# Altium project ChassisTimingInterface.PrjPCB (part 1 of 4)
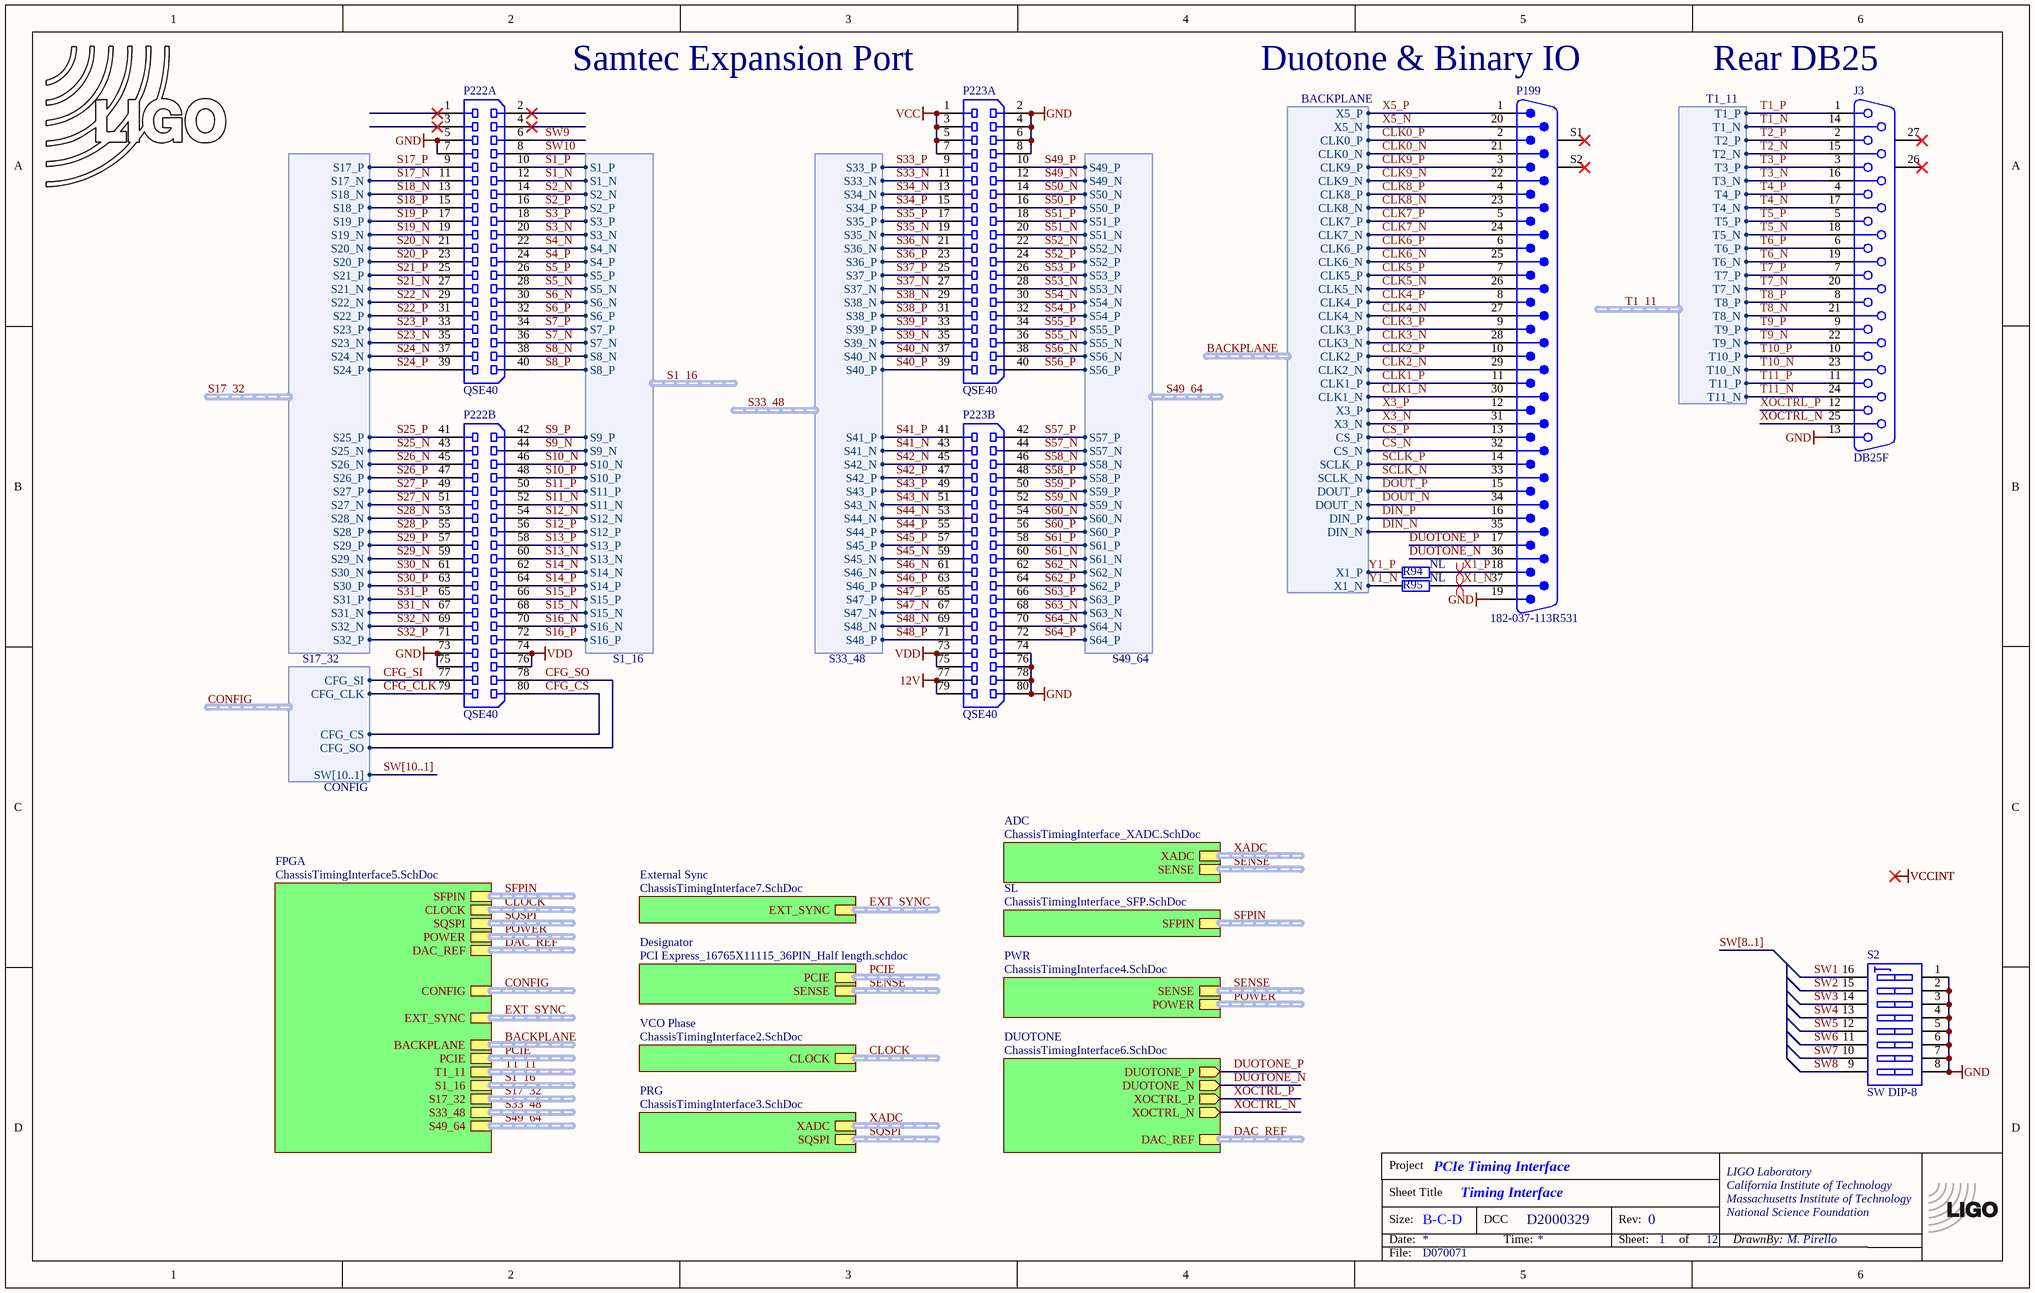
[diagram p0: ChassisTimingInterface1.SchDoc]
SHEETSIZE: B-C-D; REV: 0; PROJECT: PCIe Timing Interface; Eng: M. Pirello; DCC: D2000329
11 sheets, 554 parts. Net scope: hierarchical (ports join the sheet entries above them; power ports are global).
Board file: PCI Express_16765X11115_36PIN_Half length.PCBDOC
Sheets:
  ChassisTimingInterface1.SchDoc
    VCO Phase = ChassisTimingInterface2.SchDoc
    PWR = ChassisTimingInterface4.SchDoc
    PRG = ChassisTimingInterface3.SchDoc
    FPGA = ChassisTimingInterface5.SchDoc
      FPGA = FPGA_ARTIX7.SchDoc
    Designator = PCI Express_16765X11115_36PIN_Half length.schdoc
    DUOTONE = ChassisTimingInterface6.SchDoc
    SL = ChassisTimingInterface_SFP.SchDoc
    External Sync = ChassisTimingInterface7.SchDoc
    ADC = ChassisTimingInterface_XADC.SchDoc

## Sheet ChassisTimingInterface1.SchDoc: Timing Interface
size B; Engineer: Daniel Sigg; DocumentNumber: 1; Revision: C; SheetNumber: 1; SheetTotal: 12; PageSetup: Record=PageOptions¦CenterHorizontal=True¦CenterVertical=True¦PrintScale=0.72¦XCorrection=1.00¦YCorrection=1.00¦PrintKind=0¦BorderSize=5000000¦LeftOffset=0¦BottomOffset=0¦Orientation=2¦PaperLength=1000¦PaperWidth=1000¦Scale=100¦PaperSource=7¦PrintQuality=-4¦MediaType=1¦DitherType=10¦PaperKind=Tabloid¦PrintScaleMode=1

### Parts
(Parts that share a designator on the sheet are numbered #1, #2 ... from top to bottom, then left to right.)
*#1  TitleBlock  (value not drawn)  (graphical)
J3  DB25F  [DB25F-RA]
LOGO1  LIGO logo  [LIGO-LOGO-SM]  (value not drawn)  (no BOM)
P199  182-037-113R531  [NORCO-182-037-113R531_V]
P222  QSE40  [QSE040]  (parts A,B of 2)
P223  QSE40  [QSE040]  (parts A,B of 2)
R94  NL  [CR1005-0402]
R95  NL  [CR1005-0402]
S2  SW DIP-8  [DIP_SW_8WAY_SMD_SIDE]

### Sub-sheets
ADC = ChassisTimingInterface_XADC.SchDoc: XADC (harness XADC), SENSE (harness SENSE)
Designator = PCI Express_16765X11115_36PIN_Half length.schdoc: PCIE (harness PCIE), SENSE (harness SENSE)
DUOTONE = ChassisTimingInterface6.SchDoc: DUOTONE_N (out), DUOTONE_P (out), XOCTRL_P (out), XOCTRL_N (out), DAC_REF (harness DAC_REF)
External Sync = ChassisTimingInterface7.SchDoc: EXT_SYNC (harness EXT_SYNC)
FPGA = ChassisTimingInterface5.SchDoc: S1_16 (harness S1_16), S17_32 (harness S17_32), S33_48 (harness S33_48), S49_64 (harness S49_64), T1_11 (harness T1_11), CLOCK (harness CLOCK), PCIE (harness PCIE), POWER (harness POWER), SQSPI (harness SQSPI), DAC_REF (harness DAC_REF), CONFIG (harness CONFIG), BACKPLANE (harness BACKPLANE), SFPIN (harness SFPIN), EXT_SYNC (harness EXT_SYNC)
PRG = ChassisTimingInterface3.SchDoc: SQSPI (harness SQSPI), XADC (harness XADC)
PWR = ChassisTimingInterface4.SchDoc: POWER (harness POWER), SENSE (harness SENSE)
SL = ChassisTimingInterface_SFP.SchDoc: SFPIN (harness SFPIN)
VCO Phase = ChassisTimingInterface2.SchDoc: CLOCK (harness CLOCK)

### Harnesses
S1_16: S1_N, S1_P, S2_N, S2_P, S3_N, S3_P, S4_N, S4_P, S5_N, S5_P, S6_N, S6_P, S7_N, S7_P, S8_N, S8_P, S9_N, S9_P, S10_N, S10_P, S11_N, S11_P, S12_N, S12_P, S13_N, S13_P, S14_N, S14_P, S15_N, S15_P, S16_N, S16_P
S17_32: S17_N, S17_P, S18_N, S18_P, S19_N, S19_P, S20_N, S20_P, S21_N, S21_P, S22_N, S22_P, S23_N, S23_P, S24_N, S24_P, S25_N, S25_P, S26_N, S26_P, S27_N, S27_P, S28_N, S28_P, S29_N, S29_P, S30_N, S30_P, S31_N, S31_P, S32_N, S32_P
S33_48: S33_P, S33_N, S34_P, S34_N, S35_P, S35_N, S36_N, S36_P, S37_P, S37_N, S38_N, S38_P, S39_P, S39_N, S40_N, S40_P, S41_P, S41_N, S42_N, S42_P, S43_P, S43_N, S44_N, S44_P, S45_P, S45_N, S46_N, S46_P, S47_P, S47_N, S48_N, S48_P
S49_64: S49_P, S49_N, S50_N, S50_P, S51_P, S51_N, S52_N, S52_P, S53_P, S53_N, S54_N, S54_P, S55_P, S55_N, S56_N, S56_P, S57_P, S57_N, S58_N, S58_P, S59_P, S59_N, S60_N, S60_P, S61_P, S61_N, S62_N, S62_P, S63_P, S63_N, S64_N, S64_P
T1_11: T1_P, T1_N, T2_P, T2_N, T3_P, T3_N, T4_P, T4_N, T5_P, T5_N, T6_P, T6_N, T7_P, T7_N, T8_P, T8_N, T9_P, T9_N, T10_P, T10_N, T11_P, T11_N
CONFIG: CFG_CLK, CFG_CS, CFG_SI, CFG_SO, SW[10..1]
BACKPLANE: DIN_N, DIN_P, DOUT_N, DOUT_P, SCLK_N, SCLK_P, CS_N, CS_P, X3_N, X3_P, CLK1_N, CLK1_P, CLK2_N, CLK2_P, CLK3_N, CLK3_P, CLK4_N, CLK4_P, CLK5_N, CLK5_P, CLK6_N, CLK6_P, CLK7_N, CLK7_P, CLK8_N, CLK8_P, CLK9_N, CLK9_P, CLK0_N, CLK0_P, X5_N, X5_P, X1_P, X1_N

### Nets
12V: P223.77 P223.79
GND: J3.13 P199.19 P222.5 P222.7 P222.73 P222.75 P222.81 P222.82 P222.83 P222.84 P222.85 P222.86 P222.87 P222.88 P223.2 P223.4 P223.6 P223.8 P223.74 P223.76 P223.78 P223.80 P223.81 P223.82 P223.83 P223.84 P223.85 P223.86 P223.87 P223.88 S2.1(A1) S2.2(A2) S2.3(A3) S2.4(A4) S2.5(A5) S2.6(A6) S2.7(A7) S2.8(A8)
VCC: P223.1 P223.3 P223.5 P223.7
VDD: P222.74 P222.76 P223.73 P223.75
CFG_CLK: P222.79 ; sheet FPGA/CONFIG.CFG_CLK
CFG_CS: P222.80 ; sheet FPGA/CONFIG.CFG_CS
CFG_SI: P222.77 ; sheet FPGA/CONFIG.CFG_SI
CFG_SO: P222.78 ; sheet FPGA/CONFIG.CFG_SO
CLK0_N: P199.21 ; sheet FPGA/BACKPLANE.CLK0_N  [project net BACKPLANE.CLK0_N]
CLK0_P: P199.2 ; sheet FPGA/BACKPLANE.CLK0_P  [project net BACKPLANE.CLK0_P]
CLK1_N: P199.30 ; sheet FPGA/BACKPLANE.CLK1_N  [project net BACKPLANE.CLK1_N]
CLK1_P: P199.11 ; sheet FPGA/BACKPLANE.CLK1_P  [project net BACKPLANE.CLK1_P]
CLK2_N: P199.29 ; sheet FPGA/BACKPLANE.CLK2_N  [project net BACKPLANE.CLK2_N]
CLK2_P: P199.10 ; sheet FPGA/BACKPLANE.CLK2_P  [project net BACKPLANE.CLK2_P]
CLK3_N: P199.28 ; sheet FPGA/BACKPLANE.CLK3_N  [project net BACKPLANE.CLK3_N]
CLK3_P: P199.9 ; sheet FPGA/BACKPLANE.CLK3_P  [project net BACKPLANE.CLK3_P]
CLK4_N: P199.27 ; sheet FPGA/BACKPLANE.CLK4_N  [project net BACKPLANE.CLK4_N]
CLK4_P: P199.8 ; sheet FPGA/BACKPLANE.CLK4_P  [project net BACKPLANE.CLK4_P]
CLK5_N: P199.26 ; sheet FPGA/BACKPLANE.CLK5_N  [project net BACKPLANE.CLK5_N]
CLK5_P: P199.7 ; sheet FPGA/BACKPLANE.CLK5_P  [project net BACKPLANE.CLK5_P]
CLK6_N: P199.25 ; sheet FPGA/BACKPLANE.CLK6_N  [project net BACKPLANE.CLK6_N]
CLK6_P: P199.6 ; sheet FPGA/BACKPLANE.CLK6_P  [project net BACKPLANE.CLK6_P]
CLK7_N: P199.24 ; sheet FPGA/BACKPLANE.CLK7_N  [project net BACKPLANE.CLK7_N]
CLK7_P: P199.5 ; sheet FPGA/BACKPLANE.CLK7_P  [project net BACKPLANE.CLK7_P]
CLK8_N: P199.23 ; sheet FPGA/BACKPLANE.CLK8_N  [project net BACKPLANE.CLK8_N]
CLK8_P: P199.4 ; sheet FPGA/BACKPLANE.CLK8_P  [project net BACKPLANE.CLK8_P]
CLK9_N: P199.22 ; sheet FPGA/BACKPLANE.CLK9_N  [project net BACKPLANE.CLK9_N]
CLK9_P: P199.3 ; sheet FPGA/BACKPLANE.CLK9_P  [project net BACKPLANE.CLK9_P]
CS_N: P199.32 ; sheet FPGA/BACKPLANE.CS_N  [project net BACKPLANE.CS_N]
CS_P: P199.13 ; sheet FPGA/BACKPLANE.CS_P  [project net BACKPLANE.CS_P]
DIN_N: P199.35 ; sheet FPGA/BACKPLANE.DIN_N  [project net BACKPLANE.DIN_N]
DIN_P: P199.16 ; sheet FPGA/BACKPLANE.DIN_P  [project net BACKPLANE.DIN_P]
DOUT_N: P199.34 ; sheet FPGA/BACKPLANE.DOUT_N  [project net BACKPLANE.DOUT_N]
DOUT_P: P199.15 ; sheet FPGA/BACKPLANE.DOUT_P  [project net BACKPLANE.DOUT_P]
DUOTONE_N: P199.36 ; sheet DUOTONE/DUOTONE_N
DUOTONE_P: P199.17 ; sheet DUOTONE/DUOTONE_P
S1_N: P222.12 ; sheet FPGA/S1_16.S1_N  [project net S1_16.S1_N]
S1_P: P222.10 ; sheet FPGA/S1_16.S1_P  [project net S1_16.S1_P]
S2_N: P222.14 ; sheet FPGA/S1_16.S2_N  [project net S1_16.S2_N]
S2_P: P222.16 ; sheet FPGA/S1_16.S2_P  [project net S1_16.S2_P]
S3_N: P222.20 ; sheet FPGA/S1_16.S3_N  [project net S1_16.S3_N]
S3_P: P222.18 ; sheet FPGA/S1_16.S3_P  [project net S1_16.S3_P]
S4_N: P222.22 ; sheet FPGA/S1_16.S4_N  [project net S1_16.S4_N]
S4_P: P222.24 ; sheet FPGA/S1_16.S4_P  [project net S1_16.S4_P]
S5_N: P222.28 ; sheet FPGA/S1_16.S5_N  [project net S1_16.S5_N]
S5_P: P222.26 ; sheet FPGA/S1_16.S5_P  [project net S1_16.S5_P]
S6_N: P222.30 ; sheet FPGA/S1_16.S6_N  [project net S1_16.S6_N]
S6_P: P222.32 ; sheet FPGA/S1_16.S6_P  [project net S1_16.S6_P]
S7_N: P222.36 ; sheet FPGA/S1_16.S7_N  [project net S1_16.S7_N]
S7_P: P222.34 ; sheet FPGA/S1_16.S7_P  [project net S1_16.S7_P]
S8_N: P222.38 ; sheet FPGA/S1_16.S8_N  [project net S1_16.S8_N]
S8_P: P222.40 ; sheet FPGA/S1_16.S8_P  [project net S1_16.S8_P]
S9_N: P222.44 ; sheet FPGA/S1_16.S9_N  [project net S1_16.S9_N]
S9_P: P222.42 ; sheet FPGA/S1_16.S9_P  [project net S1_16.S9_P]
S10_N: P222.46 ; sheet FPGA/S1_16.S10_N
S10_P: P222.48 ; sheet FPGA/S1_16.S10_P
S11_N: P222.52 ; sheet FPGA/S1_16.S11_N
S11_P: P222.50 ; sheet FPGA/S1_16.S11_P
S12_N: P222.54 ; sheet FPGA/S1_16.S12_N
S12_P: P222.56 ; sheet FPGA/S1_16.S12_P
S13_N: P222.60 ; sheet FPGA/S1_16.S13_N
S13_P: P222.58 ; sheet FPGA/S1_16.S13_P
S14_N: P222.62 ; sheet FPGA/S1_16.S14_N
S14_P: P222.64 ; sheet FPGA/S1_16.S14_P
S15_N: P222.68 ; sheet FPGA/S1_16.S15_N
S15_P: P222.66 ; sheet FPGA/S1_16.S15_P
S16_N: P222.70 ; sheet FPGA/S1_16.S16_N
S16_P: P222.72 ; sheet FPGA/S1_16.S16_P
S17_N: P222.11 ; sheet FPGA/S17_32.S17_N  [project net S17_32.S17_N]
S17_P: P222.9 ; sheet FPGA/S17_32.S17_P  [project net S17_32.S17_P]
S18_N: P222.13 ; sheet FPGA/S17_32.S18_N  [project net S17_32.S18_N]
S18_P: P222.15 ; sheet FPGA/S17_32.S18_P  [project net S17_32.S18_P]
S19_N: P222.19 ; sheet FPGA/S17_32.S19_N  [project net S17_32.S19_N]
S19_P: P222.17 ; sheet FPGA/S17_32.S19_P  [project net S17_32.S19_P]
S20_N: P222.21 ; sheet FPGA/S17_32.S20_N  [project net S17_32.S20_N]
S20_P: P222.23 ; sheet FPGA/S17_32.S20_P  [project net S17_32.S20_P]
S21_N: P222.27 ; sheet FPGA/S17_32.S21_N  [project net S17_32.S21_N]
S21_P: P222.25 ; sheet FPGA/S17_32.S21_P  [project net S17_32.S21_P]
S22_N: P222.29 ; sheet FPGA/S17_32.S22_N  [project net S17_32.S22_N]
S22_P: P222.31 ; sheet FPGA/S17_32.S22_P  [project net S17_32.S22_P]
S23_N: P222.35 ; sheet FPGA/S17_32.S23_N  [project net S17_32.S23_N]
S23_P: P222.33 ; sheet FPGA/S17_32.S23_P  [project net S17_32.S23_P]
S24_N: P222.37 ; sheet FPGA/S17_32.S24_N  [project net S17_32.S24_N]
S24_P: P222.39 ; sheet FPGA/S17_32.S24_P  [project net S17_32.S24_P]
S25_N: P222.43 ; sheet FPGA/S17_32.S25_N  [project net S17_32.S25_N]
S25_P: P222.41 ; sheet FPGA/S17_32.S25_P  [project net S17_32.S25_P]
S26_N: P222.45 ; sheet FPGA/S17_32.S26_N  [project net S17_32.S26_N]
S26_P: P222.47 ; sheet FPGA/S17_32.S26_P  [project net S17_32.S26_P]
S27_N: P222.51 ; sheet FPGA/S17_32.S27_N  [project net S17_32.S27_N]
S27_P: P222.49 ; sheet FPGA/S17_32.S27_P  [project net S17_32.S27_P]
S28_N: P222.53 ; sheet FPGA/S17_32.S28_N  [project net S17_32.S28_N]
S28_P: P222.55 ; sheet FPGA/S17_32.S28_P  [project net S17_32.S28_P]
S29_N: P222.59 ; sheet FPGA/S17_32.S29_N  [project net S17_32.S29_N]
S29_P: P222.57 ; sheet FPGA/S17_32.S29_P  [project net S17_32.S29_P]
S30_N: P222.61 ; sheet FPGA/S17_32.S30_N  [project net S17_32.S30_N]
S30_P: P222.63 ; sheet FPGA/S17_32.S30_P  [project net S17_32.S30_P]
S31_N: P222.67 ; sheet FPGA/S17_32.S31_N  [project net S17_32.S31_N]
S31_P: P222.65 ; sheet FPGA/S17_32.S31_P  [project net S17_32.S31_P]
S32_N: P222.69 ; sheet FPGA/S17_32.S32_N  [project net S17_32.S32_N]
S32_P: P222.71 ; sheet FPGA/S17_32.S32_P  [project net S17_32.S32_P]
S33_N: P223.11 ; sheet FPGA/S33_48.S33_N  [project net S33_48.S33_N]
S33_P: P223.9 ; sheet FPGA/S33_48.S33_P  [project net S33_48.S33_P]
S34_N: P223.13 ; sheet FPGA/S33_48.S34_N  [project net S33_48.S34_N]
S34_P: P223.15 ; sheet FPGA/S33_48.S34_P  [project net S33_48.S34_P]
S35_N: P223.19 ; sheet FPGA/S33_48.S35_N  [project net S33_48.S35_N]
S35_P: P223.17 ; sheet FPGA/S33_48.S35_P  [project net S33_48.S35_P]
S36_N: P223.21 ; sheet FPGA/S33_48.S36_N  [project net S33_48.S36_N]
S36_P: P223.23 ; sheet FPGA/S33_48.S36_P  [project net S33_48.S36_P]
S37_N: P223.27 ; sheet FPGA/S33_48.S37_N  [project net S33_48.S37_N]
S37_P: P223.25 ; sheet FPGA/S33_48.S37_P  [project net S33_48.S37_P]
S38_N: P223.29 ; sheet FPGA/S33_48.S38_N  [project net S33_48.S38_N]
S38_P: P223.31 ; sheet FPGA/S33_48.S38_P  [project net S33_48.S38_P]
S39_N: P223.35 ; sheet FPGA/S33_48.S39_N  [project net S33_48.S39_N]
S39_P: P223.33 ; sheet FPGA/S33_48.S39_P  [project net S33_48.S39_P]
S40_N: P223.37 ; sheet FPGA/S33_48.S40_N  [project net S33_48.S40_N]
S40_P: P223.39 ; sheet FPGA/S33_48.S40_P  [project net S33_48.S40_P]
S41_N: P223.43 ; sheet FPGA/S33_48.S41_N  [project net S33_48.S41_N]
S41_P: P223.41 ; sheet FPGA/S33_48.S41_P  [project net S33_48.S41_P]
S42_N: P223.45 ; sheet FPGA/S33_48.S42_N  [project net S33_48.S42_N]
S42_P: P223.47 ; sheet FPGA/S33_48.S42_P  [project net S33_48.S42_P]
S43_N: P223.51 ; sheet FPGA/S33_48.S43_N  [project net S33_48.S43_N]
S43_P: P223.49 ; sheet FPGA/S33_48.S43_P  [project net S33_48.S43_P]
S44_N: P223.53 ; sheet FPGA/S33_48.S44_N  [project net S33_48.S44_N]
S44_P: P223.55 ; sheet FPGA/S33_48.S44_P  [project net S33_48.S44_P]
S45_N: P223.59 ; sheet FPGA/S33_48.S45_N  [project net S33_48.S45_N]
S45_P: P223.57 ; sheet FPGA/S33_48.S45_P  [project net S33_48.S45_P]
S46_N: P223.61 ; sheet FPGA/S33_48.S46_N  [project net S33_48.S46_N]
S46_P: P223.63 ; sheet FPGA/S33_48.S46_P  [project net S33_48.S46_P]
S47_N: P223.67 ; sheet FPGA/S33_48.S47_N  [project net S33_48.S47_N]
S47_P: P223.65 ; sheet FPGA/S33_48.S47_P  [project net S33_48.S47_P]
S48_N: P223.69 ; sheet FPGA/S33_48.S48_N  [project net S33_48.S48_N]
S48_P: P223.71 ; sheet FPGA/S33_48.S48_P  [project net S33_48.S48_P]
S49_N: P223.12 ; sheet FPGA/S49_64.S49_N  [project net S49_64.S49_N]
S49_P: P223.10 ; sheet FPGA/S49_64.S49_P  [project net S49_64.S49_P]
S50_N: P223.14 ; sheet FPGA/S49_64.S50_N  [project net S49_64.S50_N]
S50_P: P223.16 ; sheet FPGA/S49_64.S50_P  [project net S49_64.S50_P]
S51_N: P223.20 ; sheet FPGA/S49_64.S51_N  [project net S49_64.S51_N]
S51_P: P223.18 ; sheet FPGA/S49_64.S51_P  [project net S49_64.S51_P]
S52_N: P223.22 ; sheet FPGA/S49_64.S52_N  [project net S49_64.S52_N]
S52_P: P223.24 ; sheet FPGA/S49_64.S52_P  [project net S49_64.S52_P]
S53_N: P223.28 ; sheet FPGA/S49_64.S53_N  [project net S49_64.S53_N]
S53_P: P223.26 ; sheet FPGA/S49_64.S53_P  [project net S49_64.S53_P]
S54_N: P223.30 ; sheet FPGA/S49_64.S54_N  [project net S49_64.S54_N]
S54_P: P223.32 ; sheet FPGA/S49_64.S54_P  [project net S49_64.S54_P]
S55_N: P223.36 ; sheet FPGA/S49_64.S55_N  [project net S49_64.S55_N]
S55_P: P223.34 ; sheet FPGA/S49_64.S55_P  [project net S49_64.S55_P]
S56_N: P223.38 ; sheet FPGA/S49_64.S56_N  [project net S49_64.S56_N]
S56_P: P223.40 ; sheet FPGA/S49_64.S56_P  [project net S49_64.S56_P]
S57_N: P223.44 ; sheet FPGA/S49_64.S57_N  [project net S49_64.S57_N]
S57_P: P223.42 ; sheet FPGA/S49_64.S57_P  [project net S49_64.S57_P]
S58_N: P223.46 ; sheet FPGA/S49_64.S58_N  [project net S49_64.S58_N]
S58_P: P223.48 ; sheet FPGA/S49_64.S58_P  [project net S49_64.S58_P]
S59_N: P223.52 ; sheet FPGA/S49_64.S59_N  [project net S49_64.S59_N]
S59_P: P223.50 ; sheet FPGA/S49_64.S59_P  [project net S49_64.S59_P]
S60_N: P223.54 ; sheet FPGA/S49_64.S60_N  [project net S49_64.S60_N]
S60_P: P223.56 ; sheet FPGA/S49_64.S60_P  [project net S49_64.S60_P]
S61_N: P223.60 ; sheet FPGA/S49_64.S61_N  [project net S49_64.S61_N]
S61_P: P223.58 ; sheet FPGA/S49_64.S61_P  [project net S49_64.S61_P]
S62_N: P223.62 ; sheet FPGA/S49_64.S62_N  [project net S49_64.S62_N]
S62_P: P223.64 ; sheet FPGA/S49_64.S62_P  [project net S49_64.S62_P]
S63_N: P223.68 ; sheet FPGA/S49_64.S63_N  [project net S49_64.S63_N]
S63_P: P223.66 ; sheet FPGA/S49_64.S63_P  [project net S49_64.S63_P]
S64_N: P223.70 ; sheet FPGA/S49_64.S64_N  [project net S49_64.S64_N]
S64_P: P223.72 ; sheet FPGA/S49_64.S64_P  [project net S49_64.S64_P]
SCLK_N: P199.33 ; sheet FPGA/BACKPLANE.SCLK_N  [project net BACKPLANE.SCLK_N]
SCLK_P: P199.14 ; sheet FPGA/BACKPLANE.SCLK_P  [project net BACKPLANE.SCLK_P]
SW1: S2.16(B1)
SW2: S2.15(B2)
SW3: S2.14(B3)
SW4: S2.13(B4)
SW5: S2.12(B5)
SW6: S2.11(B6)
SW7: S2.10(B7)
SW8: S2.9(B8)
SW9: P222.6
SW10: P222.8
T1_N: J3.14 ; sheet FPGA/T1_11.T1_N  [project net T1_11.T1_N]
T1_P: J3.1 ; sheet FPGA/T1_11.T1_P  [project net T1_11.T1_P]
T2_N: J3.15 ; sheet FPGA/T1_11.T2_N  [project net T1_11.T2_N]
T2_P: J3.2 ; sheet FPGA/T1_11.T2_P  [project net T1_11.T2_P]
T3_N: J3.16 ; sheet FPGA/T1_11.T3_N  [project net T1_11.T3_N]
T3_P: J3.3 ; sheet FPGA/T1_11.T3_P  [project net T1_11.T3_P]
T4_N: J3.17 ; sheet FPGA/T1_11.T4_N  [project net T1_11.T4_N]
T4_P: J3.4 ; sheet FPGA/T1_11.T4_P  [project net T1_11.T4_P]
T5_N: J3.18 ; sheet FPGA/T1_11.T5_N  [project net T1_11.T5_N]
T5_P: J3.5 ; sheet FPGA/T1_11.T5_P  [project net T1_11.T5_P]
T6_N: J3.19 ; sheet FPGA/T1_11.T6_N  [project net T1_11.T6_N]
T6_P: J3.6 ; sheet FPGA/T1_11.T6_P  [project net T1_11.T6_P]
T7_N: J3.20 ; sheet FPGA/T1_11.T7_N  [project net T1_11.T7_N]
T7_P: J3.7 ; sheet FPGA/T1_11.T7_P  [project net T1_11.T7_P]
T8_N: J3.21 ; sheet FPGA/T1_11.T8_N  [project net T1_11.T8_N]
T8_P: J3.8 ; sheet FPGA/T1_11.T8_P  [project net T1_11.T8_P]
T9_N: J3.22 ; sheet FPGA/T1_11.T9_N  [project net T1_11.T9_N]
T9_P: J3.9 ; sheet FPGA/T1_11.T9_P  [project net T1_11.T9_P]
T10_N: J3.23 ; sheet FPGA/T1_11.T10_N
T10_P: J3.10 ; sheet FPGA/T1_11.T10_P
T11_N: J3.24 ; sheet FPGA/T1_11.T11_N
T11_P: J3.11 ; sheet FPGA/T1_11.T11_P
X1_N: P199.37 R95.2
X1_P: P199.18 R94.2
X3_N: P199.31 ; sheet FPGA/BACKPLANE.X3_N  [project net BACKPLANE.X3_N]
X3_P: P199.12 ; sheet FPGA/BACKPLANE.X3_P  [project net BACKPLANE.X3_P]
X5_N: P199.20 ; sheet FPGA/BACKPLANE.X5_N  [project net BACKPLANE.X5_N]
X5_P: P199.1 ; sheet FPGA/BACKPLANE.X5_P  [project net BACKPLANE.X5_P]
XOCTRL_N: J3.25 ; sheet DUOTONE/XOCTRL_N
XOCTRL_P: J3.12 ; sheet DUOTONE/XOCTRL_P
Y1_N: R95.1 ; sheet FPGA/BACKPLANE.X1_N  [project net BACKPLANE.X1_N]
Y1_P: R94.1 ; sheet FPGA/BACKPLANE.X1_P  [project net BACKPLANE.X1_P]

Not connected (* = marked no-connect by the designer): J3 26(MH1)* 27(MH2)*; P199 S1* S2*; P222 1* 2* 3* 4*

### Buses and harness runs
bus SW[8..1]
bus SW[10..1]
harness BACKPLANE = sheet FPGA/BACKPLANE
harness CLOCK = sheet FPGA/CLOCK
harness CLOCK = sheet VCO Phase/CLOCK
harness CONFIG = sheet FPGA/CONFIG
harness DAC_REF = sheet DUOTONE/DAC_REF
harness DAC_REF = sheet FPGA/DAC_REF
harness EXT_SYNC = sheet External Sync/EXT_SYNC
harness EXT_SYNC = sheet FPGA/EXT_SYNC
harness PCIE = sheet Designator/PCIE
harness PCIE = sheet FPGA/PCIE
harness POWER = sheet FPGA/POWER
harness POWER = sheet PWR/POWER
harness S1_16 = sheet FPGA/S1_16
harness S17_32 = sheet FPGA/S17_32
harness S33_48 = sheet FPGA/S33_48
harness S49_64 = sheet FPGA/S49_64
harness SENSE = sheet ADC/SENSE
harness SENSE = sheet Designator/SENSE
harness SENSE = sheet PWR/SENSE
harness SFPIN = sheet FPGA/SFPIN
harness SFPIN = sheet SL/SFPIN
harness SQSPI = sheet FPGA/SQSPI
harness SQSPI = sheet PRG/SQSPI
harness T1_11 = sheet FPGA/T1_11
harness XADC = sheet ADC/XADC
harness XADC = sheet PRG/XADC

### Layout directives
differential pair: X1_N, X1_P

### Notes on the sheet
- (near P223) Samtec Expansion Port
- (near P199) Duotone & Binary IO
- (near J3) Rear DB25

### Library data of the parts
J3 = DB25F: Receptacle Assembly, 25 Position, Right Angle, .318 Series; Part Number: A32128-ND
LOGO1 = LIGO_logo
P199 = CMP-2000-05512-1: Economy Version Right Angle D-Sub Connector, 5 A, -55 to 105 degC, 37-Pin THD, RoHS, Tray; Manufacturer: Norcomp; Other Related Documents: 182-037-113R531MaterialDeclaration; Gender: Male; Product Training Modules: D-SubConnectors; Package Version: 03/2005, Rev. 9; Flange Feature: Housing/Shell(4-40); Catalog Drawings: 182SeriesFront182SeriesSide; Associated Product: 160-37MA-ND-DUSTCOVERFORD-SUB37MALE; Mating Products: 3237FE-ND-CONNDSUBRCPT37POSSTRSLDCUP3237FER-ND-CONNDSUBRCPT37POSSTRSLDCUP237FE-ND-CONNDSUBRCPT37POSSTRSLDCUP237FER-ND-CONNDSUBRCPT37POSSTRSLDCUP1237FE-ND-CONNDSUBRCPT37POSSTRSLDCUP2237FER-ND-CONNDSUBRCPT37POSSTRSLDCUP2237FE-ND-CONNDSUBRCPT37POSSTRSLDCUP1237FER-ND-CONNDSUBRCPT37POSSTRSLDCUP186-037-292L001-ND-CONNDSUBRCPT37POSSTRIDC186-037-292L551-ND-CONNDSUBRCPT37POSSTRIDC; Online Catalog: 182Series; 3D Model: 182-037-113.pdf182-037-113Ryy1.stp182-037-113Ryy1.igs; Current Rating: 5A; Number of Positions: 37; Connector Type: Plug,MalePins; Other Names: 182-37ME182037113R531
P222 P223 = SAMTEC_QSE40: Samtec hi-speed socket, 0.8mm, 80 pins; Part Number: SAM8124-ND
R94 R95 = ChipRes1: Resistor, surface mount; Tolerance: 1%
S2 = SW DIP-8: DIP Switch, 8 Position, SPST; Part Number: CKN6128CT-ND; Side Part: CKN6147-ND

## Sheet ChassisTimingInterface2.SchDoc: VCO & Phase Detector
size B; DocumentNumber: 2; Revision: C; SheetNumber: 2; SheetTotal: 12
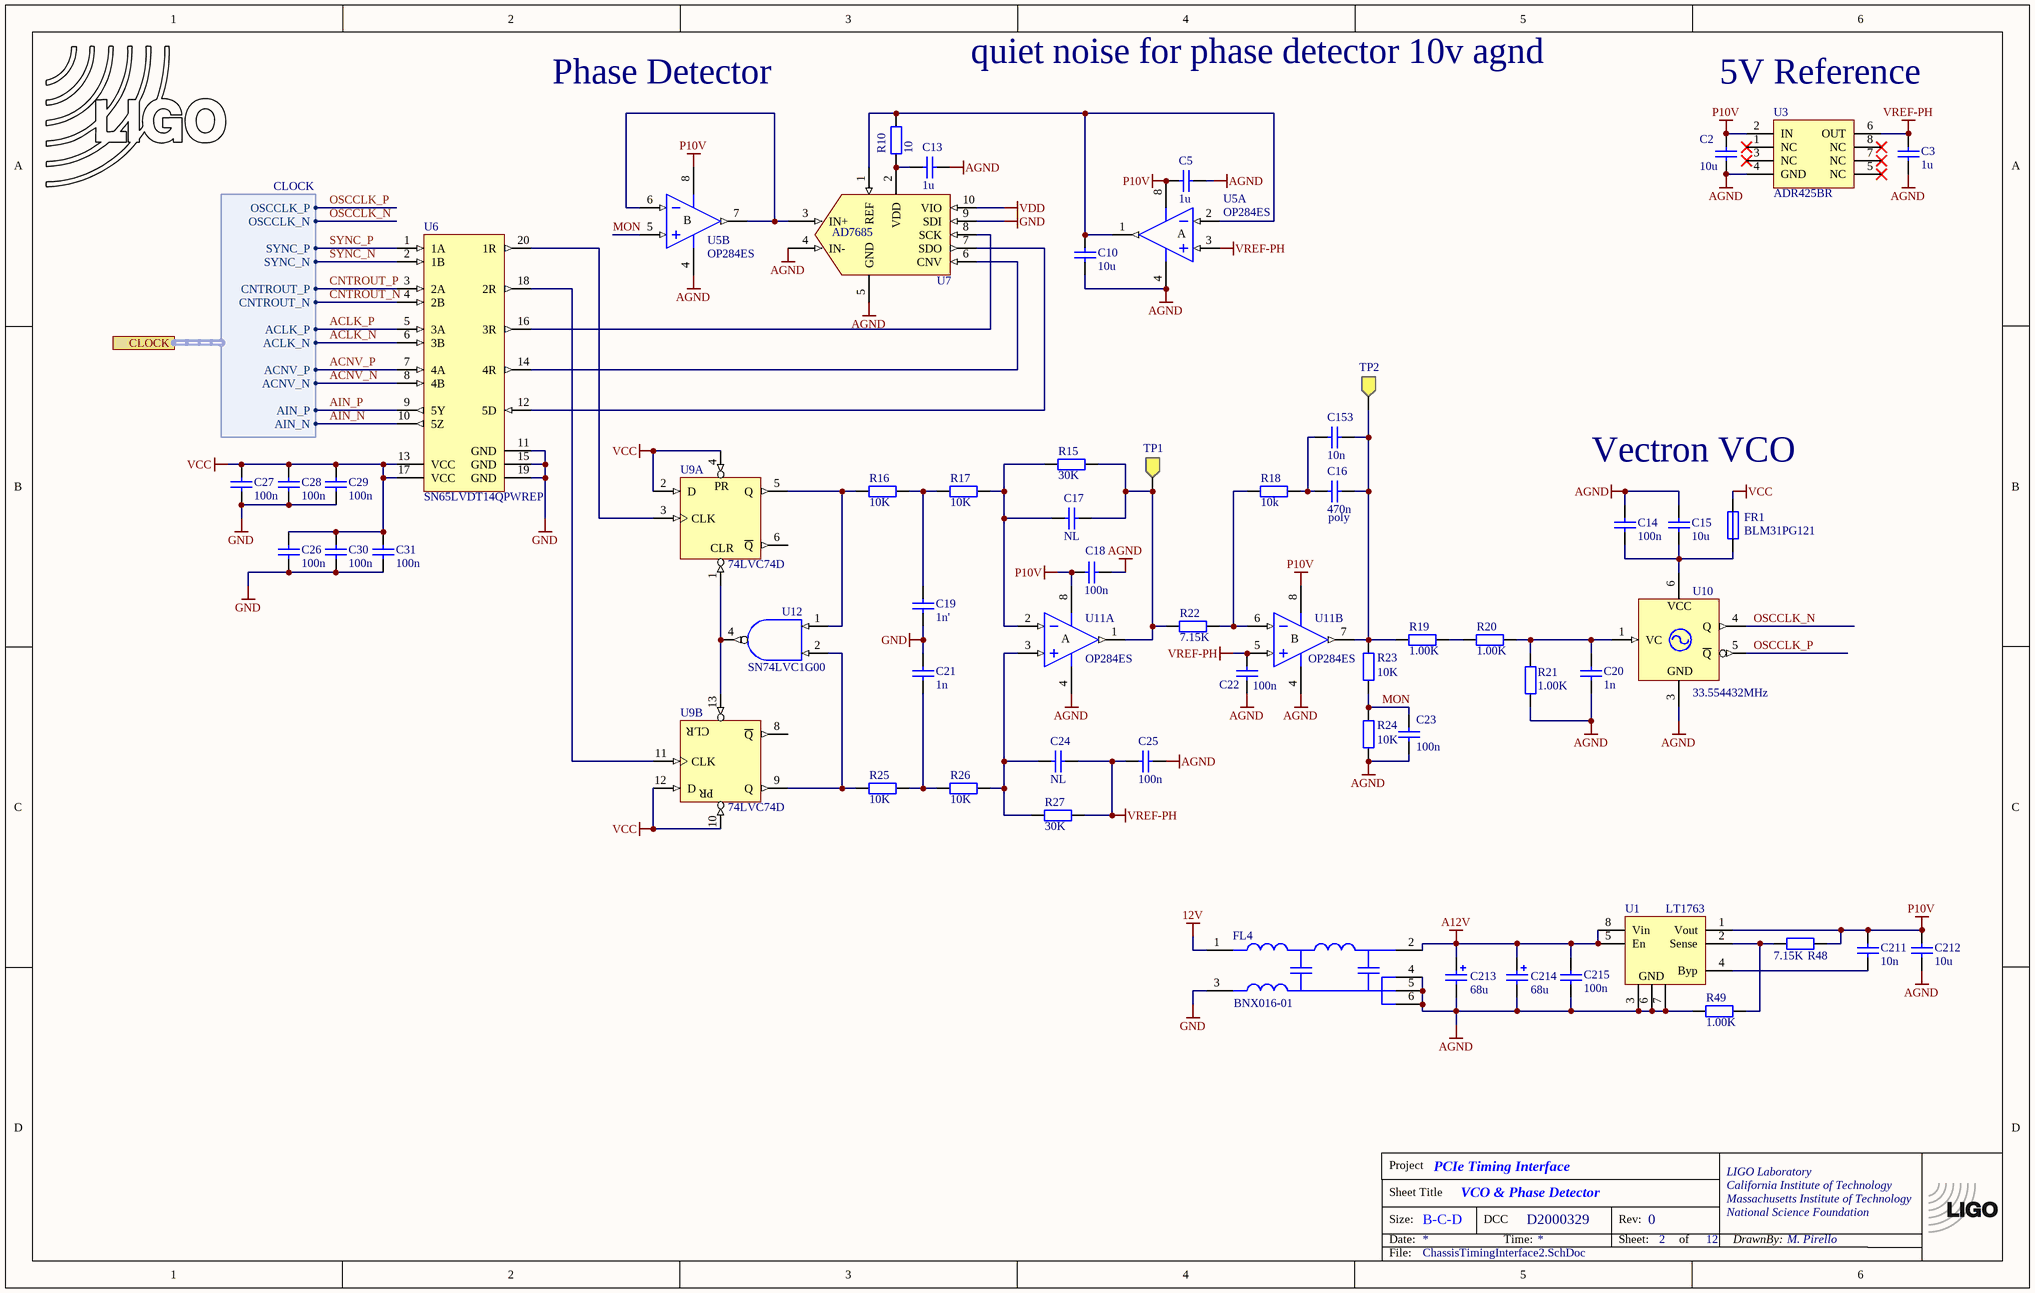
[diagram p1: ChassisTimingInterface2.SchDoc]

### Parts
(Parts that share a designator on the sheet are numbered #1, #2 ... from top to bottom, then left to right.)
*?#1  TitleBlock  (value not drawn)  (graphical)
C2  10u  [CC3216-1206]
C3  1u  [CC2013-0805]
C5  1u  [CC2013-0805]
C10  10u  [CC3216-1206]
C13  1u  [CC2013-0805]
C14  100n  [CC2013-0805]
C15  10u  [CC2013-0805]
C16  470n  [CA053035]
C17  NL  [CC2013-0805]
C18  100n  [CC2013-0805]
C19  1n'  [CC2013-0805]
C20  1n  [CC2013-0805]
C21  1n  [CC2013-0805]
C22  100n  [CC2013-0805]
C23  100n  [CC2013-0805]
C24  NL  [CC2013-0805]
C25  100n  [CC2013-0805]
C26  100n  [CC2013-0805]
C27  100n  [CC2013-0805]
C28  100n  [CC2013-0805]
C29  100n  [CC2013-0805]
C30  100n  [CC2013-0805]
C31  100n  [CC2013-0805]
C153  10n  [CC2013-0805]
C211  10n  [CC2013-0805]
C212  10u  [CC3216-1206]
C213  68u  [TC7343-2917]
C214  68u  [TC7343-2917]
C215  100n  [CC2013-0805]
FL4  BNX016-01  [MURA-BNX016-01_V]
FR1  BLM31PG121  [CC3216-1206]
LOGO2  LIGO logo  [LIGO_LOGO]  (value not drawn)  (graphical)
R10  10  [CR2012-0805]
R15  30K  [CR2012-0805]
R16  10K  [CR2012-0805]
R17  10K  [CR2012-0805]
R18  10k  [CR2012-0805]
R19  1.00K  [CR2012-0805]
R20  1.00K  [CR2012-0805]
R21  1.00K  [CR2012-0805]
R22  7.15K  [CR2012-0805]
R23  10K  [CR2012-0805]
R24  10K  [CR2012-0805]
R25  10K  [CR2012-0805]
R26  10K  [CR2012-0805]
R27  30K  [CR2012-0805]
R48  7.15K  [CR2012-0805]
R49  1.00K  [CR2012-0805]
TP1  Testpoint  [TP1-YLW]  (value not drawn)
TP2  Testpoint  [TP1-YLW]  (value not drawn)
U1  LT1763  [SO-G8]
U3  ADR425BR  [SO-G8]
U5  OP284ES  [SO-8_N]  (parts A,B of 2)
U6  SN65LVDT14QPWREP  [PW0020A_N]
U7  AD7685  [TSSO3x5-G10]
U9  74LVC74D  [TSSOP14]  (parts A,B of 2)
U10  33.554432MHz  [VECTRON_C5310]
U11  OP284ES  [SO-8_N]  (parts A,B of 2)
U12  SN74LVC1G00  [SO-G5/E2.4]

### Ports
CLOCK (harness CLOCK)

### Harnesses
CLOCK: OSCCLK_N, OSCCLK_P, CNTROUT_N, CNTROUT_P, SYNC_N, SYNC_P, ACLK_P, ACLK_N, ACNV_P, ACNV_N, AIN_P, AIN_N

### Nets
12V: FL4.1(B)
A12V: C213.1 C214.1 C215.2 FL4.2(CB) U1.5(En) U1.8(Vin)
AGND: C2.2 C3.1 C5.1 C10.2 C13.1 C14.1 C15.1 C18.1 C20.2 C22.1 C23.1 C25.1 C212.2 C213.2 C214.2 C215.1 FL4.4(CG) FL4.5(CG) FL4.6(CG) R21.2 R24.2 R49.2 U1.3(GND) U1.6(GND) U1.7(GND) U3.4(GND) U5.4(V-) U7.4(IN-) U7.5(GND) U10.3(GND) U11.4(V-)
GND: C19.2 C21.1 C26.1 C27.1 C28.1 C29.1 C30.1 C31.1 FL4.3(PSG) U6.11(GND) U6.15(GND) U6.19(GND) U7.9(SDI) U9.7(GND) U12.3(GND)
P10V: C2.1 C5.2 C18.2 C211.1 C212.1 R48.2 U1.1(Vout) U3.2(IN) U5.8(V+) U11.8(V+)
VCC: C26.2 C27.2 C28.2 C29.2 C30.2 C31.2 FR1.2 U6.13(VCC) U6.17(VCC) U9.2(D) U9.4(PR) U9.10(PR) U9.12(D) U9.14(VCC) U12.5(VCC)
VDD: U7.10(VIO)
VREF-PH: C3.2 C22.2 C24.1 C25.2 R27.2 U3.6(OUT) U5.3(IN+) U11.5(IN+)
ACLK_N: U6.6(3B) ; port CLOCK.ACLK_N  [project net CLOCK.ACLK_N]
ACLK_P: U6.5(3A) ; port CLOCK.ACLK_P  [project net CLOCK.ACLK_P]
ACNV_N: U6.8(4B) ; port CLOCK.ACNV_N  [project net CLOCK.ACNV_N]
ACNV_P: U6.7(4A) ; port CLOCK.ACNV_P  [project net CLOCK.ACNV_P]
AIN_N: U6.10(5Z) ; port CLOCK.AIN_N  [project net CLOCK.AIN_N]
AIN_P: U6.9(5Y) ; port CLOCK.AIN_P  [project net CLOCK.AIN_P]
CNTROUT_N: U6.4(2B) ; port CLOCK.CNTROUT_N  [project net CLOCK.CNTROUT_N]
CNTROUT_P: U6.3(2A) ; port CLOCK.CNTROUT_P  [project net CLOCK.CNTROUT_P]
MON: C23.2 R23.2 R24.1 U5.5(IN+)
OSCCLK_N: U10.4(Q) ; port CLOCK.OSCCLK_N  [project net CLOCK.OSCCLK_N]
OSCCLK_P: U10.5(~{Q}) ; port CLOCK.OSCCLK_P  [project net CLOCK.OSCCLK_P]
SYNC_N: U6.2(1B) ; port CLOCK.SYNC_N  [project net CLOCK.SYNC_N]
SYNC_P: U6.1(1A) ; port CLOCK.SYNC_P  [project net CLOCK.SYNC_P]
NetC10_1: C10.1 R10.2 U5.1(OUT) U5.2(IN-) U7.1(REF)
NetC13_2: C13.2 R10.1 U7.2(VDD)
NetC14_2: C14.2 C15.2 FR1.1 U10.6(VDD)
NetC16_1: C16.1 C153.2 R18.2
NetC16_2: C16.2 C153.1 R19.2 R23.1 TP2.1 U11.7(OUT)
NetC17_1: C17.1 R15.2 R22.1 TP1.1 U11.1(OUT)
NetC17_2: C17.2 R15.1 R17.2 U11.2(IN-)
NetC19_1: C19.1 R16.2 R17.1
NetC20_1: C20.1 R20.1 R21.1 U10.1(VC)
NetC21_2: C21.2 R25.2 R26.1
NetC24_2: C24.2 R26.2 R27.1 U11.3(IN+)
NetC211_2: C211.2 U1.4(Byp)
NetR16_1: R16.1 U9.5(Q) U12.1
NetR18_1: R18.1 R22.2 U11.6(IN-)
NetR19_1: R19.1 R20.2
NetR25_1: R25.1 U9.9(Q) U12.2
NetR48_1: R48.1 R49.1 U1.2(Sense)
NetU5_6: U5.6(IN-) U5.7(OUT) U7.3(IN+)
NetU6_12: U6.12(5D) U7.7(SDO)
NetU6_14: U6.14(4R) U7.6(CNV)
NetU6_16: U6.16(3R) U7.8(SCK)
NetU6_18: U6.18(2R) U9.11(CLK)
NetU6_20: U6.20(1R) U9.3(CLK)
NetU9_1: U9.1(CLR) U9.13(CLR) U12.4

Not connected (* = marked no-connect by the designer): U3 1(NC)* 3(NC)* 5(NC)* 7(NC)* 8(NC)*; U9 6(~{Q}) 8(~{Q}); U10 2(NC)

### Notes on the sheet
- Phase Detector
- quiet noise for phase detector 10v agnd
- 5V Reference
- Vectron VCO
- (near C16) poly

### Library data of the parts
C2 C3 C5 C10 C13-C15 C17-C31 C153 = ChipCap: Capacitor, surface mount; Tolerance: 10%
C16 = CapFilmAxial: Film Capacitor, axial lead; Tolerance: 1%; Voltage Rating: 50V
C211 = ChipCap: Capacitor, surface mount; Part Number: 490-1642-1-ND; Tolerance: 10%
C212 = ChipCap: Capacitor, surface mount; Part Number: PCC2414CT-ND; Tolerance: 10%; Voltage Rating: 25V
C213 C214 = ChipTantalum: Tantalum capacitor, surface mount; Part Number: 399-3908-1-ND; Tolerance: 20%; Voltage Rating: 25V
C215 = ChipCap: Capacitor, surface mount; Part Number: 478-1395-1-ND; Tolerance: 10%
FL4 = CMP-2000-05960-1: Block Type EMIFIL(R) Reference Specification, 15 A, 25 V, -40 to 125 degC, 6-Pin THD, RoHS, Bulk; Manufacturer: Murata; Maximum Current Rating: 15A; Operating Frequency: 100kHz→1GHz; Maximum Voltage Rating: 25Vdc
FR1 = BLM31PG121SN1: ferrite bead, 120Ohm at 100MHz, 1206
LOGO2 = LIGO_logo
R10 R15-R27 = ChipRes1: Resistor, surface mount; Tolerance: 1%
R48 = ChipRes1: Resistor, surface mount; Part Number: RG20P7.15KBCT-ND; Tolerance: 0.1%
R49 = ChipRes1: Resistor, surface mount; Part Number: RG20P1.0KBCT-ND; Tolerance: 0.1%
TP1 TP2 = TP_SIGNAL: Testpoint, yellow; Part Number: 5009K-ND
U1 = LT1763: Positive voltage regulator; Part Number: LT1763CS8#PBF-ND
U3 = ADR292ER: Low-Noise Micropower Precision Voltage Reference; Part Number: ADR425BRZ-ND
U5 U11 = OP284ES: Precision Rail-to-Rail Input and Output Operational Amplifier
U6 = CMP-0327-00205-3: 125 Mbps Enhanced Product Memorystick? Interconnect Extender Chipset with LVDS and LVTTL, 1 Tx and 4 Rx, -55 to +125 degC, 20-pin TSSOP (PW), Green (RoHS & no Sb/Br); Part-to-Part Skew(Max)(ps): 1000; Manufacturer: Texas Instruments; No. of Tx: 1; ESD HBM(kV): 12; ICC(Max)(mA): 25; Signaling Rate(Mbps): 125; Output Signal: LVDS, LVTTL; SubFamily: LVDS PHY (<800Mbps); No. of Rx: 4
U7 = AD7685: 16 bit ADC, 250kSPS, pseudo differential, serial
U9 = 74F74PC: Dual D-Type Positive Edge-Triggered Flip-Flop; Part Number: 296-1240-5-ND
U10 = VECTRON_C5310: Voltage controlled crystal oscillator; Part Number: C5310-D105-SV033-RFL-B1-33.554432MHz
U12 = SN74LVC1G00: Part Number: 296-9845-1-ND

## Sheet ChassisTimingInterface4.SchDoc: Power Supply
size B; DocumentNumber: 5; Revision: C; SheetNumber: 5; SheetTotal: 12
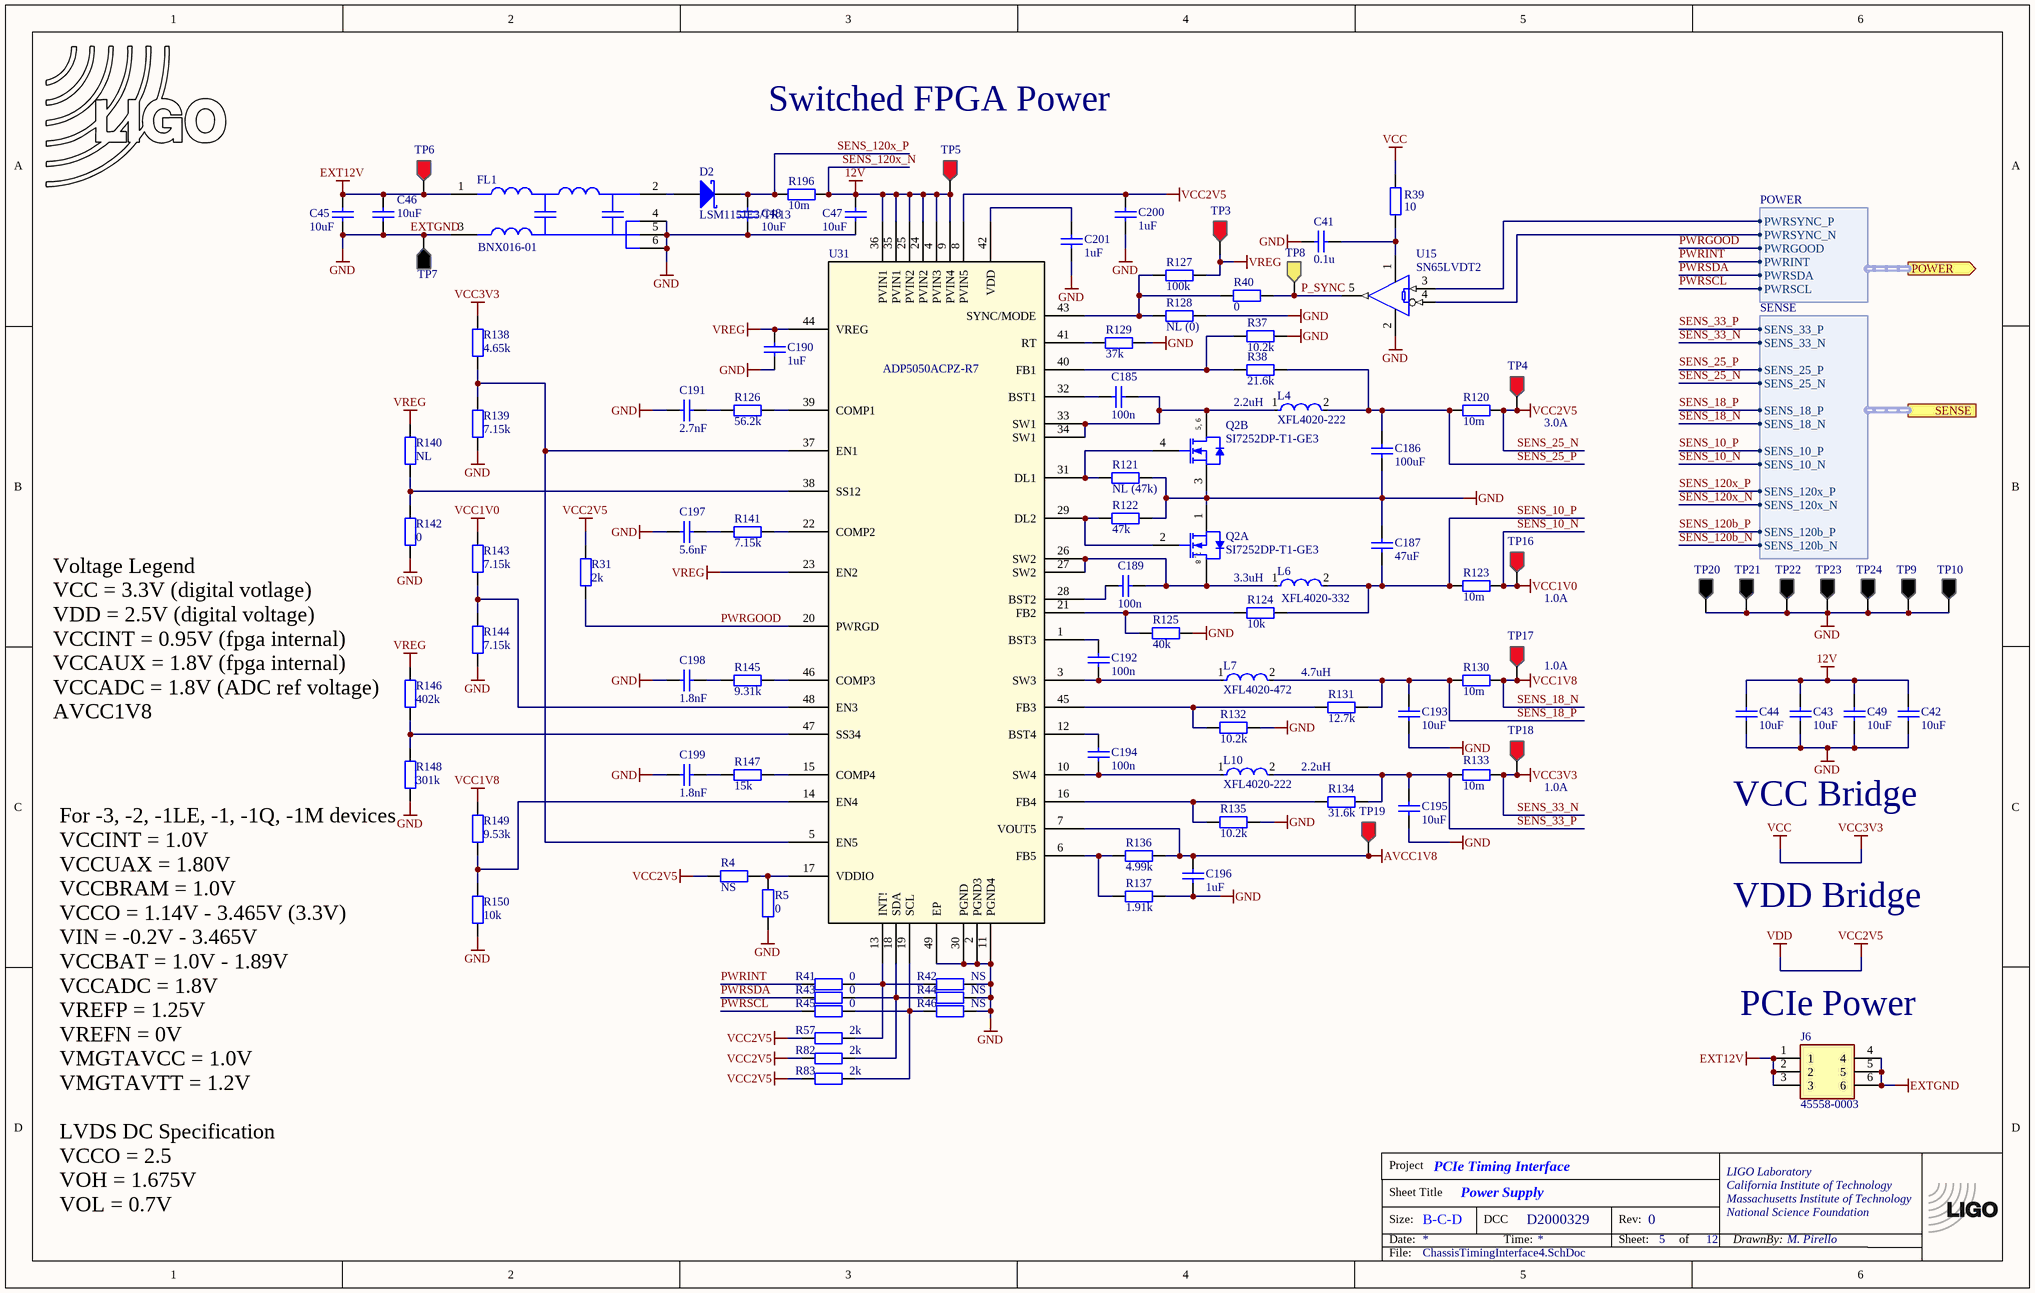
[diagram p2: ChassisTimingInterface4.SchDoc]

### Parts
(Parts that share a designator on the sheet are numbered #1, #2 ... from top to bottom, then left to right.)
*#2  TitleBlock  (value not drawn)  (graphical)
C41  0.1u  [CC1608-0603]
C42  10uF  [CC2013-0805]
C43  10uF  [CC2013-0805]
C44  10uF  [CC2013-0805]
C45  10uF  [CC2013-0805]
C46  10uF  [CC2013-0805]
C47  10uF  [CC2013-0805]
C48  10uF  [CC2013-0805]
C49  10uF  [CC2013-0805]
C185  100n  [CC1005-0402]
C186  100uF  [CC3225-1210]
C187  47uF  [CC3225-1210]
C189  100n  [CC1005-0402]
C190  1uF  [CC1005-0402]
C191  2.7nF  [CC1005-0402]
C192  100n  [CC1005-0402]
C193  10uF  [CC2013-0805]
C194  100n  [CC1005-0402]
C195  10uF  [CC2013-0805]
C196  1uF  [CC1005-0402]
C197  5.6nF  [CC1005-0402]
C198  1.8nF  [CC1005-0402]
C199  1.8nF  [CC1005-0402]
C200  1uF  [CC1005-0402]
C201  1uF  [CC1005-0402]
D2  LSM115JE3/TR13  [MCSM-DO-214BA-2_L]
FL1  BNX016-01  [MURA-BNX016-01_V]
J6  45558-0003  [455580003]
L4  XFL4020-222  [FP-XAL40-MFG]
L6  XFL4020-332  [FP-XAL40-MFG]
L7  XFL4020-472  [FP-XAL40-MFG]
L10  XFL4020-222  [FP-XAL40-MFG]
LOGO4#1  LIGO logo  [LIGO_LOGO]  (value not drawn)  (graphical)
Q2  SI7252DP-T1-GE3  [VISH-POWERPAKSO-8_A_V]  (parts A,B of 2)
R4  NS  [CR1005-0402]
R5  0  [CR1005-0402]
R31  2k  [CR1005-0402]
R37  10.2k  [CR1005-0402]
R38  21.6k  [CR1005-0402]
R39  10  [CR1005-0402]
R40  0  [CR1005-0402]
R41  0  [CR1005-0402]
R42  NS  [CR1005-0402]
R43  0  [CR1005-0402]
R44  NS  [CR1005-0402]
R45  0  [CR1005-0402]
R46  NS  [CR1005-0402]
R57  2k  [CR1005-0402]
R82  2k  [CR1005-0402]
R83  2k  [CR1005-0402]
R120  10m  [CR3225-1210]
R121  NL (47k)  [CR1005-0402]
R122  47k  [CR1005-0402]
R123  10m  [CR3225-1210]
R124  10k  [CR1005-0402]
R125  40k  [CR1005-0402]
R126  56.2k  [CR1005-0402]
R127  100k  [CR1005-0402]
R128  NL (0)  [CR1005-0402]
R129  37k  [CR1005-0402]
R130  10m  [CR3225-1210]
R131  12.7k  [CR1005-0402]
R132  10.2k  [CR1005-0402]
R133  10m  [CR3225-1210]
R134  31.6k  [CR1005-0402]
R135  10.2k  [CR1005-0402]
R136  4.99k  [CR1005-0402]
R137  1.91k  [CR1005-0402]
R138  4.65k  [CR1005-0402]
R139  7.15k  [CR1005-0402]
R140  NL  [CR1005-0402]
R141  7.15k  [CR1005-0402]
R142  0  [CR1005-0402]
R143  7.15k  [CR1005-0402]
R144  7.15k  [CR1005-0402]
R145  9.31k  [CR1005-0402]
R146  402k  [CR1005-0402]
R147  15k  [CR1005-0402]
R148  301k  [CR1005-0402]
R149  9.53k  [CR1005-0402]
R150  10k  [CR1005-0402]
R196  10m  [CR3225-1210]
TP3  Testpoint  [TP1-RED]  (value not drawn)
TP4  Testpoint  [TP1-RED]  (value not drawn)
TP5  Testpoint  [TP1-RED]  (value not drawn)
TP6  Testpoint  [TP1-RED]  (value not drawn)
TP7  Testpoint  [TP1-BLK]  (value not drawn)
TP8  Testpoint  [TP1-YLW]  (value not drawn)
TP9  Testpoint  [TP1-BLK]  (value not drawn)
TP10  Testpoint  [TP1-BLK]  (value not drawn)
TP16  Testpoint  [TP1-RED]  (value not drawn)
TP17  Testpoint  [TP1-RED]  (value not drawn)
TP18  Testpoint  [TP1-RED]  (value not drawn)
TP19  Testpoint  [TP1-RED]  (value not drawn)
TP20  Testpoint  [TP1-BLK]  (value not drawn)
TP21  Testpoint  [TP1-BLK]  (value not drawn)
TP22  Testpoint  [TP1-BLK]  (value not drawn)
TP23  Testpoint  [TP1-BLK]  (value not drawn)
TP24  Testpoint  [TP1-BLK]  (value not drawn)
U15  SN65LVDT2  [SO-G5/E2.4]
U31  ADP5050ACPZ-R7  [CP-48-13_L]

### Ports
POWER (out, harness POWER), SENSE (harness SENSE)

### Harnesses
POWER: PWRSYNC_N, PWRSYNC_P, PWRGOOD, PWRINT, PWRSDA, PWRSCL
SENSE: SENS_33_P, SENS_33_N, SENS_25_P, SENS_25_N, SENS_18_P, SENS_18_N, SENS_10_P, SENS_10_N, SENS_120x_P, SENS_120x_N, SENS_120b_P, SENS_120b_N

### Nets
12V: C42.1 C43.1 C44.1 C47.1 C49.1 R196.2 TP5.1 U31.4(PVIN3) U31.9(PVIN4) U31.24(PVIN2) U31.25(PVIN2) U31.35(PVIN1) U31.36(PVIN1) ; port SENSE.SENS_120x_N, port SENSE.SENS_120b_N  [also labelled SENS_120b_N, SENS_120x_N]
AVCC1V8: C196.2 R136.2 TP19.1 U31.7(VOUT5)
EXT12V: C45.1 C46.1 FL1.1(B) J6.1 J6.2 J6.3 TP6.1
GND: C41.2 C42.2 C43.2 C44.2 C45.2 C46.2 C47.2 C48.2 C49.2 C186.1 C187.2 C190.2 C191.1 C193.1 C195.1 C196.1 C197.1 C198.1 C199.1 C200.1 C201.1 FL1.3(PSG) FL1.4(CG) FL1.5(CG) FL1.6(CG) J6.4 J6.5 J6.6 Q2.1(S1) Q2.3(S2) R5.1 R37.2 R42.2 R44.2 R46.2 R121.2 R122.2 R125.2 R128.2 R129.2 R132.2 R135.2 R137.2 R139.1 R142.1 R144.1 R148.1 R150.1 TP7.1 TP9.1 TP10.1 TP20.1 TP21.1 TP22.1 TP23.1 TP24.1 U15.2(GND) U31.2(PGND3) U31.11(PGND4) U31.30(PGND) U31.49(EP)  [also labelled EXTGND]
SENS_10_N: R123.2 R143.2 TP16.1 ; port SENSE.SENS_10_N  [also labelled VCC1V0]  [project net VCCINT]
VCC: R39.2 R133.2 R138.2 TP18.1 ; port SENSE.SENS_33_N  [also labelled SENS_33_N, VCC3V3]
VCC1V8: R130.2 R149.2 TP17.1 ; port SENSE.SENS_18_N  [also labelled SENS_18_N]
VDD: C200.2 R4.2 R31.2 R57.1 R82.1 R83.1 R120.2 TP4.1 U31.8(PVIN5) ; port SENSE.SENS_25_N  [also labelled SENS_25_N, VCC2V5]
VREG: C190.1 R127.2 R140.2 R146.2 TP3.1 U31.23(EN2) U31.44(VREG)
P_SYNC: R40.2 TP8.1 U15.5(R)
POWER.PWRSYNC_N: U15.4(B) ; port POWER.PWRSYNC_N
POWER.PWRSYNC_P: U15.3(A) ; port POWER.PWRSYNC_P
PWRGOOD: R31.1 U31.20(PWRGD) ; port POWER.PWRGOOD  [project net POWER.PWRGOOD]
PWRINT: R41.1 ; port POWER.PWRINT  [project net POWER.PWRINT]
PWRSCL: R45.1 ; port POWER.PWRSCL  [project net POWER.PWRSCL]
PWRSDA: R43.1 ; port POWER.PWRSDA  [project net POWER.PWRSDA]
SENS_10_P: C187.1 L6.2 R123.1 R124.2 ; port SENSE.SENS_10_P  [project net SENSE.SENS_10_P]
SENS_18_P: C193.2 L7.2 R130.1 R131.2 ; port SENSE.SENS_18_P  [project net SENSE.SENS_18_P]
SENS_25_P: C186.2 L4.2 R38.2 R120.1 ; port SENSE.SENS_25_P  [project net SENSE.SENS_25_P]
SENS_33_P: C195.2 L10.2 R133.1 R134.2 ; port SENSE.SENS_33_P  [project net SENSE.SENS_33_P]
SENS_120x_P: C48.1 D2.2(K) R196.1 ; port SENSE.SENS_120x_P  [project net SENSE.SENS_120x_P]
NetC41_1: C41.1 R39.1 U15.1(VCC)
NetC185_1: C185.1 U31.32(BST1)
NetC185_2: C185.2 L4.1 Q2.5(D2) Q2.6(D2) U31.33(SW1) U31.34(SW1)
NetC189_1: C189.1 U31.28(BST2)
NetC189_2: C189.2 L6.1 Q2.7(D1) Q2.8(D1) U31.26(SW2) U31.27(SW2)
NetC191_2: C191.2 R126.1
NetC192_1: C192.1 L7.1 U31.3(SW3)
NetC192_2: C192.2 U31.1(BST3)
NetC194_1: C194.1 L10.1 U31.10(SW4)
NetC194_2: C194.2 U31.12(BST4)
NetC197_2: C197.2 R141.1
NetC198_2: C198.2 R145.1
NetC199_2: C199.2 R147.1
NetC201_2: C201.2 U31.42(VDD)
NetD2_1: D2.1(A) FL1.2(CB)
NetQ2_2: Q2.2(G1) R122.1 U31.29(DL2)
NetQ2_4: Q2.4(G2) R121.1 U31.31(DL1)
NetR4_1: R4.1 R5.2 U31.17(VDDIO)
NetR37_1: R37.1 R38.1 U31.40(FB1)
NetR40_1: R40.1 R127.1 R128.1 U31.43(SYNC/MODE)
NetR41_2: R41.2 R42.1 R57.2 U31.13(INT!)
NetR43_2: R43.2 R44.1 R82.2 U31.18(SDA)
NetR45_2: R45.2 R46.1 R83.2 U31.19(SCL)
NetR124_1: R124.1 R125.1 U31.21(FB2)
NetR126_2: R126.2 U31.39(COMP1)
NetR129_1: R129.1 U31.41(RT)
NetR131_1: R131.1 R132.1 U31.45(FB3)
NetR134_1: R134.1 R135.1 U31.16(FB4)
NetR136_1: R136.1 R137.1 U31.6(FB5)
NetR138_1: R138.1 R139.2 U31.5(EN5) U31.37(EN1)
NetR140_1: R140.1 R142.2 U31.38(SS12)
NetR141_2: R141.2 U31.22(COMP2)
NetR143_1: R143.1 R144.2 U31.48(EN3)
NetR145_2: R145.2 U31.46(COMP3)
NetR146_1: R146.1 R148.2 U31.47(SS34)
NetR147_2: R147.2 U31.15(COMP4)
NetR149_1: R149.1 R150.2 U31.14(EN4)

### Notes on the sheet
- Switched FPGA Power
- 2.2uH
- 3.0A
- 3.3uH
- 1.0A
- 4.7uH
- (near TP17) 1.0A
- Voltage Legend
  VCC = 3.3V (digital votlage)
  VDD = 2.5V (digital voltage)
  VCCINT = 0.95V (fpga internal)
  VCCAUX = 1.8V (fpga internal)
  VCCADC = 1.8V (ADC ref voltage)
  AVCC1V8
- VCC Bridge
- VDD Bridge
- (near J6) PCIe Power
- (near R148) For -3, -2, -1LE, -1, -1Q, -1M devices
  VCCINT = 1.0V
  VCCUAX = 1.80V
  VCCBRAM = 1.0V
  VCCO = 1.14V - 3.465V (3.3V)
  VIN = -0.2V - 3.465V
  VCCBAT = 1.0V - 1.89V
  VCCADC = 1.8V
  VREFP = 1.25V
  VREFN = 0V
  VMGTAVCC = 1.0V
  VMGTAVTT = 1.2V
  LVDS DC Specification
  VCCO = 2.5
  VOH = 1.675V
  VOL = 0.7V

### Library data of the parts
C41-C49 C185-C187 C189-C201 = ChipCap: Capacitor, surface mount; Tolerance: 10%
D2 = CMP-2000-06604-1: Ultra Low Forward Voltage Schottky Rectifier, 15 V, -55 to 100 degC, 2-Pin Molded, RoHS, Tape and Reel; Manufacturer: MicrosemiCorporation; Voltage - Forward (Vf) (Max) @ If: 220mV@1A; Current - Average Rectified (Io): 1A; Voltage - DC Reverse (Vr) (Max): 15V; Current - Reverse Leakage @ Vr: 10mA@15V; Speed: FastRecovery=200mA(Io)
FL1 = CMP-2000-05960-1: as FL4 on sheet ChassisTimingInterface2
J6 = 45558-0003: Connector; Manufacturer_Name: Molex; Allied_Number: 71464452
L4 L10 = CMP-11268-000008-1: INDUCTOR, 2.2uH; Manufacturer Part Number: XAL4040-103MEC; Manufacturer: Coilcraft; Inductance: 10uH; Saturation Current: 3A; Value: 10uH; Test Frequency: 1MHz; Self Resonant Frequency: 24MHz; Core Material: Composite; Tolerance: 20%; Series Resistance: 92.4mΩ; Standoff Height: 0.06mm; Rms Current: 3.1A; Automotive Grade: Grade 1; Shielding: true
L6 = CMP-11268-000008-1: INDUCTOR, 3.3uH; Manufacturer Part Number: XAL4040-103MEC; Manufacturer: Coilcraft; Inductance: 10uH; Saturation Current: 3A; Value: 10uH; Test Frequency: 1MHz; Self Resonant Frequency: 24MHz; Core Material: Composite; Tolerance: 20%; Series Resistance: 92.4mΩ; Standoff Height: 0.06mm; Rms Current: 3.1A; Automotive Grade: Grade 1; Shielding: true
L7 = CMP-11268-000008-1: INDUCTOR, 4.7uH; Manufacturer Part Number: XAL4040-103MEC; Manufacturer: Coilcraft; Inductance: 10uH; Saturation Current: 3A; Value: 10uH; Test Frequency: 1MHz; Self Resonant Frequency: 24MHz; Core Material: Composite; Tolerance: 20%; Series Resistance: 92.4mΩ; Standoff Height: 0.06mm; Rms Current: 3.1A; Automotive Grade: Grade 1; Shielding: true
LOGO4#1 = LIGO_logo
Q2 = CMP-2000-07602-1: Dual N-Channel (D-S) MOSFET, 100 V, 36.7 A, -55 to 150 degC, 8-Pin SMD, RoHS, Tape and Reel; Manufacturer: Vishay Semiconductor
R4 R5 R31 R37-R46 R57 R82 R83 R120-R150 R196 = ChipRes1: Resistor, surface mount; Tolerance: 1%
TP3-TP6 TP16-TP19 = TP_POSITIVE: Testpoint, red; Part Number: 5005K-ND
TP7 TP9 TP10 TP20-TP24 = TP_GND: Testpoint, black; Part Number: 5006K-ND
TP8 = TP_SIGNAL: Testpoint, yellow; Part Number: 5009K-ND
U15 = SN65LVDT2DBV: Single LVDS Receiver with 100 Ohm termination; Part Number: 296-6896-1-ND
U31 = ADP5050ACPZ-R7: Artix 7 Power Supply; Manufacturer_Part_Number: ADP5052ACPZ-R7; Vendor: Analog Devices Inc; Built_By: EMA_UL_Team

## Sheet ChassisTimingInterface3.SchDoc: JTAG & SPI Flash
size B; DocumentNumber: 4; Revision: C; SheetNumber: 4; SheetTotal: 12
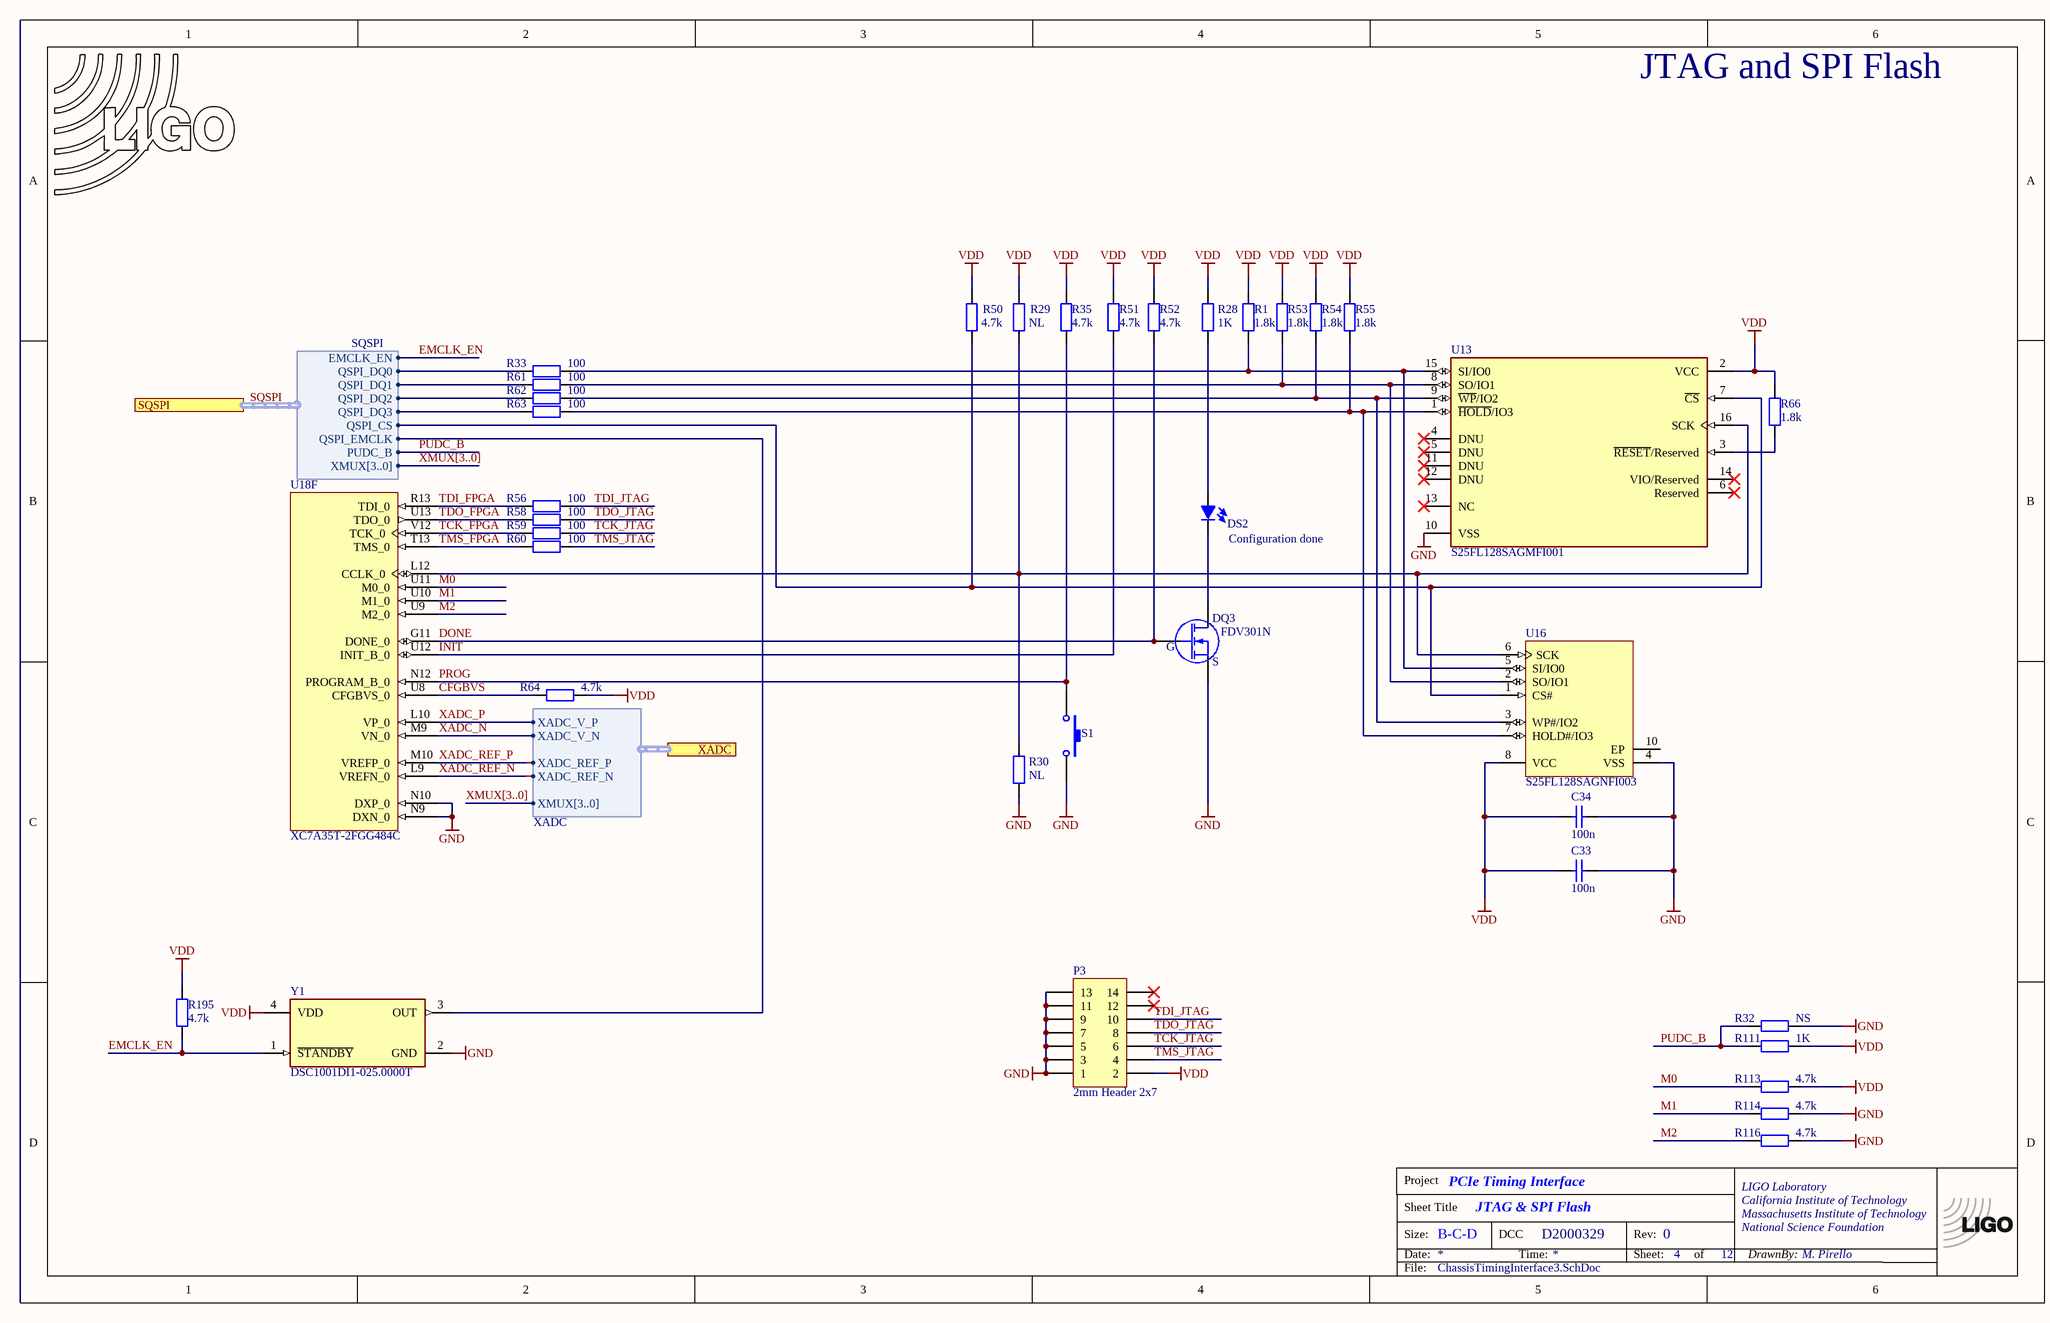
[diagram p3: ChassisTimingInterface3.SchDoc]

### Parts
(Parts that share a designator on the sheet are numbered #1, #2 ... from top to bottom, then left to right.)
*?#2  TitleBlock  (value not drawn)  (graphical)
C33  100n  [CC1005-0402]
C34  100n  [CC1005-0402]
DS2  LED  [LED-0805]  (value not drawn)
LOGO3  LIGO logo  [LIGO_LOGO]  (value not drawn)  (graphical)
P3  2mm Header 2x7  [2MM_HDR2X7_RA]
Q3  FDV301N  [SO-G3/C2.25]
R1  1.8k  [CR1005-0402]
R28  1K  [CR1005-0402]
R29  NL  [CR1005-0402]
R30  NL  [CR1005-0402]
R32  NS  [CR1005-0402]
R33  100  [CR1005-0402]
R35  4.7k  [CR1005-0402]
R50  4.7k  [CR1005-0402]
R51  4.7k  [CR1005-0402]
R52  4.7k  [CR1005-0402]
R53  1.8k  [CR1005-0402]
R54  1.8k  [CR1005-0402]
R55  1.8k  [CR1005-0402]
R56  100  [CR1005-0402]
R58  100  [CR1005-0402]
R59  100  [CR1005-0402]
R60  100  [CR1005-0402]
R61  100  [CR1005-0402]
R62  100  [CR1005-0402]
R63  100  [CR1005-0402]
R64  4.7k  [CR1005-0402]
R66  1.8k  [CR1005-0402]
R111  1K  [CR1005-0402]
R113  4.7k  [CR1005-0402]
R114  4.7k  [CR1005-0402]
R116  4.7k  [CR1005-0402]
R195  4.7k  [CR1005-0402]
S1  B3SN-3112P  [SW_SMD_6MM]  (value not drawn)
U13  S25FL128SAGMFI001  [FP-002-15547-MFG]
U16  S25FL128SAGNFI003  [SPSN-WSON-8_L]
U18  XC7A35T-2FGG484C  [FGG484]  (part F of 12)
Y1  DSC1001DI1-025.0000T  [FP-CDFN2520-4LD-PL-1-MFG]

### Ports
SQSPI (harness SQSPI), XADC (harness XADC)

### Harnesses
SQSPI: QSPI_DQ0, QSPI_DQ1, QSPI_DQ2, QSPI_DQ3, QSPI_CS, QSPI_EMCLK, PUDC_B, XMUX[3..0], EMCLK_EN
XADC: XADC_REF_P, XADC_V_N, XADC_V_P, XMUX[3..0], XADC_REF_N

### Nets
GND: C33.1 C34.1 P3.1 P3.3 P3.5 P3.7 P3.9 P3.11 P3.13 Q3.2(S) R30.2 R32.2 R114.2 R116.2 S1.3 S1.5 U13.10(VSS) U16.4(VSS) U18.N9(DXN_0) U18.N10(DXP_0) Y1.2(GND)
VDD: C33.2 C34.2 P3.2 R1.2 R28.1 R29.1 R35.2 R50.1 R51.2 R52.2 R53.2 R54.2 R55.2 R64.2 R66.2 R111.2 R113.2 R195.1 U13.2(VCC) U16.8(VCC) Y1.4(VDD)
CFGBVS: R64.1 U18.U8(CFGBVS_0)
DONE: Q3.1(G) R52.1 U18.G11(DONE_0)
EMCLK_EN: R195.2 Y1.1(~{STANDBY}) ; port SQSPI.EMCLK_EN  [project net SQSPI.EMCLK_EN]
INIT: R51.1 U18.U12(INIT_B_0)
M0: R113.1 U18.U11(M0_0)
M1: R114.1 U18.U10(M1_0)
M2: R116.1 U18.U9(M2_0)
PROG: R35.1 S1.1 U18.N12(PROGRAM_B_0)
PUDC_B: R32.1 R111.1 ; port SQSPI.PUDC_B  [project net SQSPI.PUDC_B]
SQSPI.QSPI_CS: R50.2 U13.7(~{CS}) U16.1(CS#) ; port SQSPI.QSPI_CS
SQSPI.QSPI_DQ0: R33.2 ; port SQSPI.QSPI_DQ0
SQSPI.QSPI_DQ1: R61.2 ; port SQSPI.QSPI_DQ1
SQSPI.QSPI_DQ2: R62.2 ; port SQSPI.QSPI_DQ2
SQSPI.QSPI_DQ3: R63.2 ; port SQSPI.QSPI_DQ3
SQSPI.QSPI_EMCLK: Y1.3(OUT) ; port SQSPI.QSPI_EMCLK
TCK_FPGA: R59.2 U18.V12(TCK_0)
TCK_JTAG: P3.6 R59.1
TDI_FPGA: R56.2 U18.R13(TDI_0)
TDI_JTAG: P3.10 R56.1
TDO_FPGA: R58.2 U18.U13(TDO_0)
TDO_JTAG: P3.8 R58.1
TMS_FPGA: R60.2 U18.T13(TMS_0)
TMS_JTAG: P3.4 R60.1
XADC_N: U18.M9(VN_0) ; port XADC.XADC_V_N  [project net XADC.XADC_V_N]
XADC_P: U18.L10(VP_0) ; port XADC.XADC_V_P  [project net XADC.XADC_V_P]
XADC_REF_N: U18.L9(VREFN_0) ; port XADC.XADC_REF_N  [project net XADC.XADC_REF_N]
XADC_REF_P: U18.M10(VREFP_0) ; port XADC.XADC_REF_P  [project net XADC.XADC_REF_P]
NetDS2_1: DS2.1(K) Q3.3(D)
NetDS2_2: DS2.2(A) R28.2
NetR1_1: R1.1 R33.1 U13.15(SI/IO0) U16.5(SI/IO0)
NetR29_2: R29.2 R30.1 U13.16(SCK) U16.6(SCK) U18.L12(CCLK_0)
NetR53_1: R53.1 R61.1 U13.8(SO/IO1) U16.2(SO/IO1)
NetR54_1: R54.1 R62.1 U13.9(~{WP}/IO2) U16.3(WP#/IO2)
NetR55_1: R55.1 R63.1 U13.1(~{HOLD}/IO3) U16.7(HOLD#/IO3)
NetR66_1: R66.1 U13.3(~{RESET}/Reserved)

Not connected (* = marked no-connect by the designer): P3 12* 14*; U13 4(DNU)* 5(DNU)* 6(Reserved)* 11(DNU)* 12(DNU)* 13(NC)* 14(VIO/Reserved)*; U16 10(EP)

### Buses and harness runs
bus XMUX[3..0]
harness SQSPI = port SQSPI

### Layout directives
differential pair: XADC.XADC_REF_N, XADC.XADC_REF_P

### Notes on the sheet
- JTAG and SPI Flash
- (near DS2) Configuration done

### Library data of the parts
C33 C34 = ChipCap: Capacitor, surface mount; Tolerance: 10%
DS2 = LED: Panel mount LED
LOGO3 = LIGO_logo
P3 = Xilinx_JTAG_Header: Xilinx JTAG header, 7-Pin, Dual row; Part Number: WM4224-ND; RA Part: WM18863-ND
Q3 = FDV301N: FDV301N, Digital FET, N-channel, SOT23; Part Number: FDV301NCT-ND
R1 R28-R30 R32 R33 R35 R50-R56 R58-R64 R66 R111 R113 R114 R116 R195 = ChipRes1: Resistor, surface mount; Tolerance: 1%
S1 = B3SN-3112P: Switch, SMD, 6mm; Part Number: SW262CT-ND
U13 = CMP-12948-000005-1: IC FLASH 128M SPI 133MHZ 16SOIC; Manufacturer: Cypress Semiconductor; Standoff Height: 0.1mm; Memory Type: FLASH,NOR; Memory Size: 128Mbits; Min Supply Voltage: 1.65V; Access Time: 8ns; Max Supply Voltage: 3.6V; Nominal Supply Current: 16-100mA
U16 = CMP-1329-00027-1: MirrorBit Flash Non-Volatile Memory CMOS 3.0 Volt Core with Versatile I/O, Serial Peripheral Interface with Multi-I/O, 128 Mbit, 133 MHz, -40 to 85 degC, 8-Pin WSON (WNG008), RoHS, Tape and Reel; Manufacturer: Spansion; Speed: 133 MHz; VCC: 2.7 to 3.6 V; OTP: 1024 B
U18 = CMP-0383-00019-1: Artix-7 FPGA, 250 User I/Os, 4 GTP, 484-Ball BGA, Speed Grade 2, Commercial Grade, Pb-Free; Manufacturer: Xilinx; Total Block RAM: 1800 Kb; GTP: 4; Available User I/O: 250; Speed Grades: 2; Logic Cells: 33280; CMTs: 5
Y1 = CMP-06255-000005-1: MEMS OSC XO 25.0000MHZ CMOS SMD; Manufacturer: Microchip Technology; Automotive Grade: Grade 3; Max Junction Temp: +150°C; Stability: 50ppm; Min Supply Voltage: 1.7V; Max Supply Voltage: 3.6V; Frequency: 25MHz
